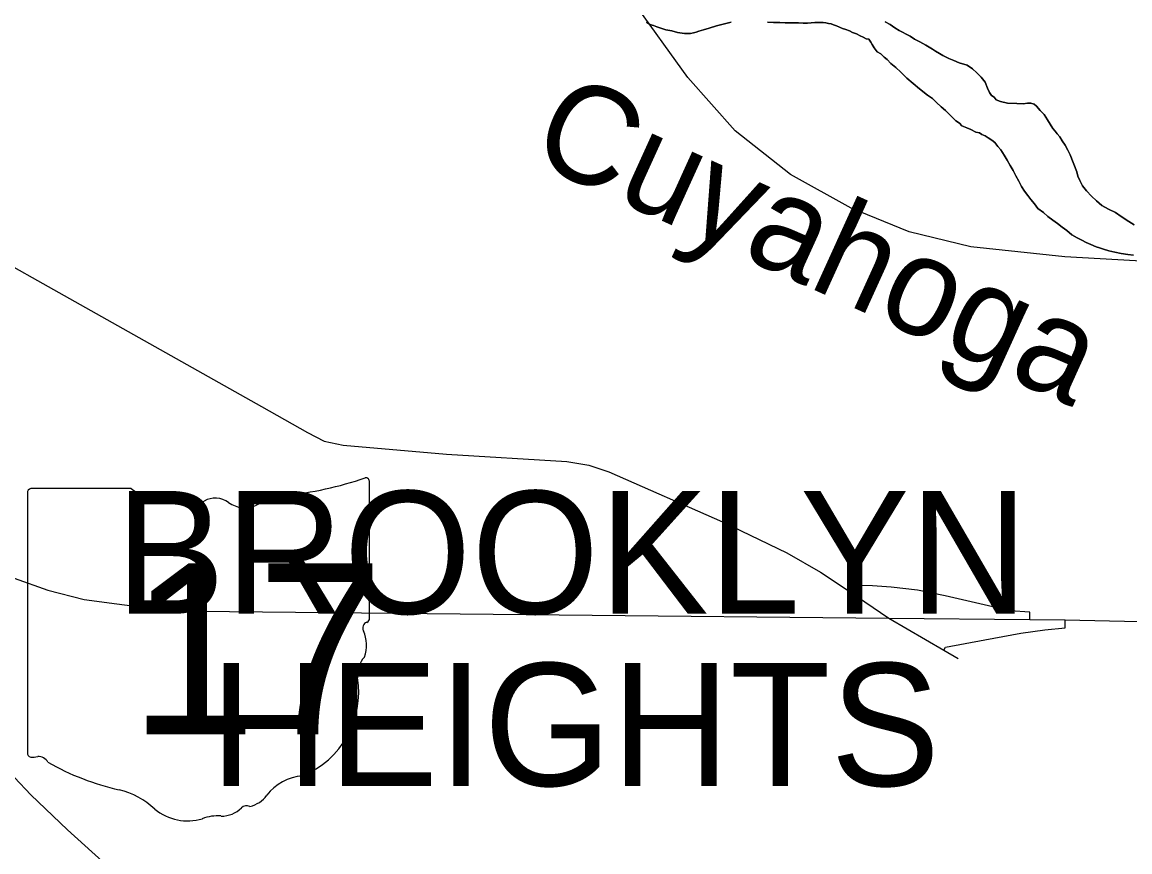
# Model space of a CAD drawing. Extents: x -561 to 1170, y 0 to 846.
# Drawn here: x 258.25 to 270.43, y 203.65 to 212.77 of the extents above; entities that cross this region are included whole.
import ezdxf

# ---------------------------------------------------------------- set-up
doc = ezdxf.new("R2010")
doc.units = 0
for name, color, linetype in [('GM_X_City_Street', 7, 'Continuous'), ('GM_X_Corporation_Text', 7, 'Continuous'), ('GM_X_Interchange_Ramps', 7, 'Continuous'), ('GM_X_Interstate_Route', 7, 'Continuous'), ('GM_X_Major_River', 7, 'Continuous'), ('GM_X_Major_River_Text', 7, 'Continuous'), ('GM_X_Rail_Line', 7, 'Continuous'), ('GM_X_State_Location', 7, 'Continuous'), ('GM_X_State_Route', 7, 'Continuous'), ('GM_X_State_Shield', 7, 'Continuous')]:
    doc.layers.add(name, color=color, linetype=linetype)

msp = doc.modelspace()

# ---------------------------------------------------------------- linework, layer by layer
at = {"layer": 'GM_X_City_Street'}
msp.add_lwpolyline([(254.362, 212.218), (254.406, 212.193), (255.693, 211.466), (260.884, 208.548), (261.389, 208.265), (261.573, 208.17), (261.781, 208.124), (262.915, 208.025), (264.238, 207.943), (264.482, 207.904), (264.702, 207.832), (265.95, 207.281), (266.656, 206.94), (267.028, 206.73), (267.341, 206.518), (267.777, 206.223), (268.385, 205.87), (268.542, 205.779)], dxfattribs=at)
at = {"layer": 'GM_X_Interchange_Ramps'}
for points in [[(269.329, 206.208), (269.33, 206.289), (269.113, 206.303), (268.397, 206.468), (268.095, 206.529), (267.803, 206.563), (267.6, 206.577), (267.379, 206.581), (267.341, 206.518)], [(268.385, 205.87), (268.401, 205.903), (268.835, 205.983), (269.231, 206.058), (269.495, 206.096), (269.716, 206.115), (269.717, 206.205)]]:
    msp.add_lwpolyline(points, dxfattribs=at)
at = {"layer": 'GM_X_Interstate_Route'}
msp.add_lwpolyline([(257.885, 204.764), (257.91, 204.738), (257.983, 204.662), (258.347, 204.282), (258.749, 203.895), (259.13, 203.551), (259.452, 203.314)], dxfattribs=at)
at = {"layer": 'GM_X_Major_River'}
for points in [[(265.114, 212.774), (265.152, 212.748), (265.19, 212.737), (265.229, 212.721), (265.272, 212.706), (265.326, 212.69), (265.392, 212.68), (265.457, 212.659), (265.533, 212.649), (265.598, 212.65), (265.63, 212.656), (265.662, 212.662), (265.689, 212.673), (265.743, 212.69), (265.803, 212.707), (265.883, 212.735), (265.959, 212.752), (266.002, 212.763), (266.045, 212.775)], [(266.045, 212.775), (266.002, 212.763), (265.959, 212.752), (265.883, 212.735), (265.803, 212.707), (265.743, 212.69), (265.689, 212.673), (265.662, 212.662), (265.63, 212.656), (265.598, 212.65), (265.533, 212.649), (265.457, 212.659), (265.392, 212.68), (265.326, 212.69), (265.272, 212.706), (265.229, 212.721), (265.19, 212.737), (265.152, 212.748), (265.114, 212.774)], [(266.446, 212.774), (266.511, 212.769), (266.581, 212.77), (266.641, 212.766), (266.7, 212.766), (266.744, 212.767), (266.787, 212.767), (266.836, 212.762), (266.884, 212.763), (266.965, 212.769), (267.014, 212.77), (267.057, 212.771), (267.085, 212.765), (267.117, 212.76), (267.144, 212.755), (267.171, 212.745), (267.204, 212.734), (267.237, 212.719), (267.269, 212.703), (267.307, 212.692), (267.346, 212.677), (267.378, 212.661), (267.422, 212.645), (267.465, 212.624), (267.498, 212.608), (267.531, 212.592), (267.558, 212.587), (267.58, 212.555), (267.597, 212.528), (267.619, 212.49), (267.652, 212.447), (267.69, 212.426), (267.728, 212.389), (267.761, 212.362), (267.8, 212.319), (267.854, 212.276), (267.909, 212.223), (267.975, 212.159), (268.046, 212.1), (268.117, 212.041), (268.205, 211.972), (268.26, 211.935), (268.304, 211.892), (268.353, 211.844), (268.402, 211.801), (268.435, 211.769), (268.517, 211.688), (268.556, 211.662), (268.583, 211.635), (268.638, 211.614), (268.681, 211.593), (268.736, 211.566), (268.774, 211.556), (268.801, 211.54), (268.839, 211.524), (268.872, 211.503), (268.91, 211.476), (268.943, 211.45), (268.976, 211.407), (269.009, 211.369)], [(269.009, 211.369), (268.976, 211.407), (268.943, 211.45), (268.91, 211.476), (268.872, 211.503), (268.839, 211.524), (268.801, 211.54), (268.774, 211.556), (268.736, 211.566), (268.681, 211.593), (268.638, 211.614), (268.583, 211.635), (268.556, 211.662), (268.517, 211.688), (268.435, 211.769), (268.402, 211.801), (268.353, 211.844), (268.304, 211.892), (268.26, 211.935), (268.205, 211.972), (268.117, 212.041), (268.046, 212.1), (267.975, 212.159), (267.909, 212.223), (267.854, 212.276), (267.8, 212.319), (267.761, 212.362), (267.728, 212.389), (267.69, 212.426), (267.652, 212.447), (267.619, 212.49), (267.597, 212.528), (267.58, 212.555), (267.558, 212.587), (267.531, 212.592), (267.498, 212.608), (267.465, 212.624), (267.422, 212.645), (267.378, 212.661), (267.346, 212.677), (267.307, 212.692), (267.269, 212.703), (267.237, 212.719), (267.204, 212.734), (267.171, 212.745), (267.144, 212.755), (267.117, 212.76), (267.085, 212.765), (267.057, 212.771), (267.014, 212.77), (266.965, 212.769), (266.884, 212.763), (266.836, 212.762), (266.787, 212.767), (266.744, 212.767), (266.7, 212.766), (266.641, 212.766), (266.581, 212.77), (266.511, 212.769), (266.446, 212.774)], [(267.892, 212.683), (267.843, 212.71), (267.794, 212.747), (267.739, 212.779)], [(267.739, 212.779), (267.794, 212.747), (267.843, 212.71), (267.892, 212.683)], [(270.476, 210.547), (270.416, 210.584), (270.334, 210.638), (270.269, 210.68), (270.192, 210.717), (270.122, 210.76), (270.061, 210.808), (270.006, 210.861), (269.952, 210.92), (269.908, 210.974), (269.88, 211.033), (269.857, 211.082), (269.846, 211.13), (269.773, 211.314), (269.745, 211.367), (269.717, 211.421), (269.684, 211.47), (269.657, 211.513), (269.629, 211.545), (269.607, 211.577), (269.58, 211.604), (269.552, 211.652), (269.524, 211.701), (269.485, 211.76), (269.441, 211.803), (269.403, 211.851), (269.376, 211.872), (269.338, 211.883), (269.305, 211.882), (269.256, 211.876), (269.186, 211.881), (269.083, 211.885), (269.007, 211.9), (268.958, 211.921), (268.936, 211.948), (268.909, 211.969), (268.887, 212.002), (268.864, 212.05), (268.836, 212.115), (268.792, 212.168), (268.748, 212.217), (268.699, 212.259), (268.639, 212.302), (268.552, 212.328), (268.492, 212.354), (268.438, 212.375), (268.4, 212.391), (268.372, 212.407), (268.334, 212.428), (268.29, 212.455), (268.258, 212.476), (268.187, 212.519), (268.121, 212.556), (268.061, 212.588), (268.012, 212.62), (267.969, 212.641), (267.93, 212.662), (267.892, 212.683)], [(267.892, 212.683), (267.93, 212.662), (267.969, 212.641), (268.012, 212.62), (268.061, 212.588), (268.121, 212.556), (268.187, 212.519), (268.258, 212.476), (268.29, 212.455), (268.334, 212.428), (268.372, 212.407), (268.4, 212.391), (268.438, 212.375), (268.492, 212.354), (268.552, 212.328), (268.639, 212.302), (268.699, 212.259), (268.748, 212.217), (268.792, 212.168), (268.836, 212.115), (268.864, 212.05), (268.887, 212.002), (268.909, 211.969), (268.936, 211.948), (268.958, 211.921), (269.007, 211.9), (269.083, 211.885), (269.186, 211.881), (269.256, 211.876), (269.305, 211.882), (269.338, 211.883), (269.376, 211.872), (269.403, 211.851), (269.441, 211.803), (269.485, 211.76), (269.524, 211.701), (269.552, 211.652), (269.58, 211.604), (269.607, 211.577), (269.629, 211.545), (269.657, 211.513), (269.684, 211.47), (269.717, 211.421), (269.745, 211.367), (269.773, 211.314), (269.846, 211.13), (269.857, 211.082), (269.88, 211.033), (269.908, 210.974), (269.952, 210.92), (270.006, 210.861), (270.061, 210.808), (270.122, 210.76), (270.192, 210.717), (270.269, 210.68), (270.334, 210.638), (270.416, 210.584), (270.476, 210.547)], [(269.009, 211.369), (269.048, 211.31), (269.081, 211.256), (269.114, 211.197), (269.147, 211.143), (269.175, 211.084), (269.209, 211.025), (269.236, 210.966), (269.27, 210.917), (269.308, 210.869), (269.341, 210.826), (269.38, 210.778), (269.418, 210.724), (269.478, 210.681), (269.528, 210.639), (269.583, 210.596), (269.632, 210.559), (269.686, 210.521), (269.736, 210.484), (269.79, 210.436), (269.85, 210.404), (269.899, 210.378), (269.949, 210.351), (269.998, 210.33), (270.057, 210.304), (270.095, 210.293), (270.139, 210.278), (270.199, 210.262), (270.264, 210.247), (270.334, 210.231), (270.405, 210.221), (270.47, 210.211)], [(270.47, 210.211), (270.405, 210.221), (270.334, 210.231), (270.264, 210.247), (270.199, 210.262), (270.139, 210.278), (270.095, 210.293), (270.057, 210.304), (269.998, 210.33), (269.949, 210.351), (269.899, 210.378), (269.85, 210.404), (269.79, 210.436), (269.736, 210.484), (269.686, 210.521), (269.632, 210.559), (269.583, 210.596), (269.528, 210.639), (269.478, 210.681), (269.418, 210.724), (269.38, 210.778), (269.341, 210.826), (269.308, 210.869), (269.27, 210.917), (269.236, 210.966), (269.209, 211.025), (269.175, 211.084), (269.147, 211.143), (269.114, 211.197), (269.081, 211.256), (269.048, 211.31), (269.009, 211.369)]]:
    msp.add_lwpolyline(points, dxfattribs=at)
at = {"layer": 'GM_X_Rail_Line'}
msp.add_lwpolyline([(281.132, 204.902), (280.928, 205.078), (278.881, 206.854), (276.707, 208.749), (276.098, 209.195), (275.587, 209.51), (274.782, 209.761), (273.922, 209.957), (269.712, 210.196), (268.679, 210.305), (268.004, 210.468), (267.363, 210.729), (266.699, 211.099), (266.09, 211.578), (265.568, 212.166), (264.959, 213.014), (262.048, 216.981)], dxfattribs=at)
at = {"layer": 'GM_X_State_Route'}
for points in [[(255.334, 208.725), (255.368, 208.693), (255.917, 208.204), (256.311, 207.851), (256.727, 207.477), (257.058, 207.241), (257.384, 207.021), (257.785, 206.823), (258.164, 206.662), (258.533, 206.529), (258.934, 206.428), (259.291, 206.382), (259.604, 206.34), (259.988, 206.304), (260.529, 206.296), (267.777, 206.223)], [(267.777, 206.223), (269.329, 206.208), (269.717, 206.205), (270.531, 206.186), (271.347, 206.179), (272.071, 206.166), (272.242, 206.163), (272.466, 206.158)]]:
    msp.add_lwpolyline(points, dxfattribs=at)
at = {"layer": 'GM_X_State_Shield'}
for p, q in [((259.449, 207.647), (258.348, 207.647)), ((262.07, 206.225), (262.07, 207.718)), ((258.311, 207.598), (258.311, 204.745)), ((262.069, 206.226), (262.07, 206.225))]:
    msp.add_line(p, q, dxfattribs=at)
for centre, radius, start, end in [((260.731, 211.536), 3.986, 275.8445, 288.9065), ((262.028, 207.724), 0.0418, 351.8621, 97.738), ((258.354, 207.604), 0.0435, 98.1301, 188.1301), ((259.711, 207.978), 0.422, 231.6195, 271.1119), ((259.851, 206.045), 1.516, 80.4867, 94.9883), ((260.195, 207.619), 0.122, 219.7921, 297.1024), ((260.374, 207.289), 0.253, 54.4667, 119.1411), ((260.701, 207.741), 0.305, 233.8562, 294.8282), ((261.239, 206.775), 0.802, 97.3462, 120.7689), ((262.06, 206.116), 0.0648, 107.944, 210.337), ((262.025, 206.219), 0.0448, 289.6038, 7.7341), ((261.648, 205.927), 0.389, 340.033, 23.6496), ((262.22, 205.601), 0.283, 136.8065, 186.9296), ((260.954, 205.411), 0.997, 292.3089, 8.9858), ((258.354, 204.739), 0.0439, 171.9584, 258.3066), ((258.361, 205.03), 0.335, 267.339, 280.6039), ((258.43, 204.58), 0.121, 29.7484, 93.2717), ((259.956, 207.143), 2.879, 240.4129, 257.1985), ((261.374, 203.944), 0.546, 94.4031, 142.5768), ((259.098, 203.463), 0.901, 47.1842, 75.836), ((260.683, 204.468), 0.322, 282.8732, 323.2771), ((260.072, 204.566), 0.572, 230.7004, 286.2918), ((260.444, 204.352), 0.305, 268.777, 315.5493), ((260.719, 204.076), 0.0857, 65.7517, 132.6484), ((260.402, 203.58), 0.47, 85.6951, 111.2099)]:
    msp.add_arc(centre, radius, start, end, dxfattribs=at)

# ---------------------------------------------------------------- texts
at = {"layer": 'GM_X_Corporation_Text'}
for s, p in [('BROOKLYN', (259.278, 206.271)), ('HEIGHTS', (260.317, 204.379))]:
    msp.add_text(s, height=1.35, rotation=0, dxfattribs=at).set_placement(p)
at = {"layer": 'GM_X_Major_River_Text'}
msp.add_text('Cuyahoga', height=1.0806, rotation=335.5806, dxfattribs=at).set_placement((263.799, 211.265))
at = {"layer": 'GM_X_State_Location'}
for s in ['s', 'r']:
    msp.add_text(s, height=0.0027, dxfattribs=at).set_placement((260.148, 205.982))
msp.add_text('17', height=0.0027, rotation=0, dxfattribs=at).set_placement((259.468, 205.785))
at = {"layer": 'GM_X_State_Shield'}
msp.add_text('17', height=1.8795, dxfattribs=at).set_placement((259.43, 204.946))

doc.saveas('drawing.dxf')
